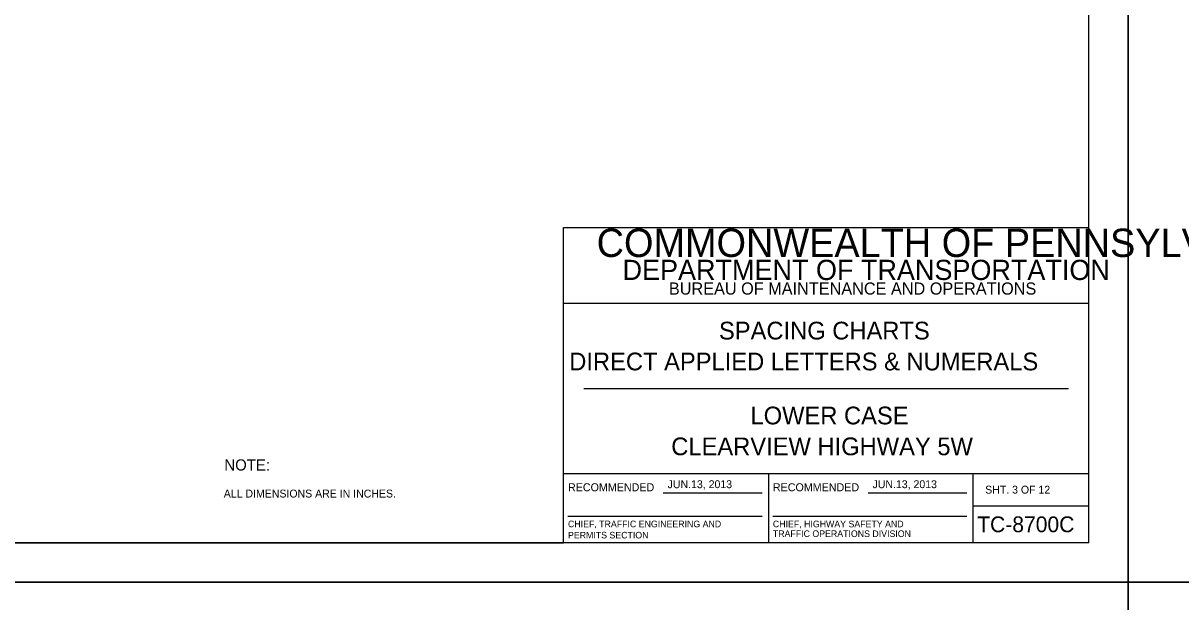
# Model space of a CAD drawing. Extents: x 638421 to 641849, y 297270 to 299646.
# Drawn here: x 639682.6 to 640123.3, y 299044.1 to 299264.3 of the extents above; entities that cross this region are included whole.
import ezdxf

# ---------------------------------------------------------------- set-up
doc = ezdxf.new("R2010")
doc.units = 0
for name, color, linetype in [('1', 7, 'Continuous'), ('2', 7, 'Continuous'), ('XCS-GRID-HVGL', 7, 'Continuous')]:
    doc.layers.add(name, color=color, linetype=linetype)

msp = doc.modelspace()

# ---------------------------------------------------------------- linework, layer by layer
at = {"layer": '1'}
for p, q in [((640088.31, 299066.63), (640088.31, 299630.63)), ((639888.31, 299066.63), (639888.31, 299186.63)), ((639888.31, 299186.63), (640088.31, 299186.63)), ((640088.31, 299157.63), (639888.31, 299157.63)), ((639896.06, 299125.31), (640080.56, 299125.31)), ((639888.31, 299093), (640088.31, 299093)), ((639966.31, 299093), (639966.31, 299066.63)), ((640044.19, 299066.63), (640044.19, 299093)), ((639926.24, 299085.57), (639963.87, 299085.57)), ((640004.24, 299085.57), (640041.87, 299085.57)), ((639889.99, 299076.68), (639963.87, 299076.68)), ((639967.99, 299076.68), (640041.87, 299076.68)), ((640044.19, 299080.63), (640088.31, 299080.63)), ((640088.31, 299066.63), (639302.31, 299066.63)), ((639302.31, 299066.63), (639888.31, 299066.63))]:
    msp.add_line(p, q, dxfattribs=at)
at = {"layer": 'XCS-GRID-HVGL'}
for points in [[(639262.31, 299645.63), (640103.31, 299645.63), (640103.31, 299051.63), (639262.31, 299051.63)], [(640103.31, 299645.63), (640944.31, 299645.63), (640944.31, 299051.63), (640103.31, 299051.63)], [(639262.31, 299051.63), (640103.31, 299051.63), (640103.31, 298457.63), (639262.31, 298457.63)], [(640103.31, 299051.63), (640944.31, 299051.63), (640944.31, 298457.63), (640103.31, 298457.63)]]:
    msp.add_lwpolyline(points, close=True, dxfattribs=at)

# ---------------------------------------------------------------- texts
at = {"layer": '1'}
for s, height, p in [('COMMONWEALTH OF PENNSYLVANIA', 10.7828, (639900.9, 299175.36)), ('DEPARTMENT OF TRANSPORTATION', 7.6837, (639910.76, 299166.61)), ('BUREAU OF MAINTENANCE AND OPERATIONS', 4.6253, (639928.41, 299161.04)), ('SPACING CHARTS', 6.75, (639947.47, 299143.97)), ('DIRECT APPLIED LETTERS & NUMERALS', 6.75, (639890.47, 299132.22)), ('LOWER CASE', 6.75, (639959.47, 299111.66)), ('CLEARVIEW HIGHWAY 5W', 6.75, (639929.3, 299099.91)), ('RECOMMENDED', 3.048, (639889.99, 299086.2)), ('RECOMMENDED', 3.048, (639967.99, 299086.2)), ('SHT. 3 OF 12', 3, (640048.82, 299085.31)), ('TC-8700C', 6, (640045.77, 299070.63)), ('CHIEF, TRAFFIC ENGINEERING AND', 2.5, (639889.99, 299072.51)), ('CHIEF, HIGHWAY SAFETY AND', 2.5, (639967.99, 299072.51)), ('PERMITS SECTION', 2.5, (639889.99, 299068.26)), ('TRAFFIC OPERATIONS DIVISION', 2.5, (639967.99, 299068.81))]:
    msp.add_text(s, height=height, dxfattribs=at).set_placement(p)
at = {"layer": '2'}
for s, height, p in [('NOTE:', 4.25, (639759.16, 299094.1)), ('JUN.13, 2013', 3, (639927.93, 299087.39)), ('JUN.13, 2013', 3, (640005.93, 299087.39)), ('ALL DIMENSIONS ARE IN INCHES.', 3, (639758.94, 299083.83))]:
    msp.add_text(s, height=height, dxfattribs=at).set_placement(p)

doc.saveas('drawing.dxf')
